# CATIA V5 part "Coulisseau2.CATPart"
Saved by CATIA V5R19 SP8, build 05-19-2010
Part number: Coulisseau2
Bounding box of the stored display mesh (mm): x -7.5 to 3.5, y -33.632 to -22.368, z -4.258 to 4.258
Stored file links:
  C:\Users\ThinkMotion\Desktop\EU_thinkMotion\iao\IAO_MMS_Groupe3\pmayet\pmayet_avant_optimisation\pmayet_avant_optimisation\Coulisseau2.CATPart
  C:\Users\ThinkMotion\Desktop\EU_thinkMotion\iao\IAO_MMS_Groupe3\pmayet\pmayet_avant_optimisation\pmayet_avant_optimisation\pmayet.CATProduct
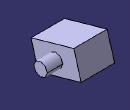
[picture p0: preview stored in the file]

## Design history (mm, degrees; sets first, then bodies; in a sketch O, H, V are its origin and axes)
Parameters
  Largeur_rainure_a = 6 mm
  Longueur_coulisseau = 10 mm
  Rayon_axe = 1.5 mm
  Epaisseu_disque = 15 mm
  Longueur_axe = 3.5 mm
Set1
  Plane1: linked copy from another document
  Line1: linked copy from another document
  Point1 "Point2": linked copy from another document
Body1 (main body)
  Sketch1 on Plane1, origin (0, 0, 0), H (0, 1, 0), V (0, 0, 1)
    line L1 (-33.6318, 1.511) -> (-24.0165, 4.2582)
    line L2 (-24.0165, 4.2582) -> (-22.3682, -1.511)
    line L3 (-22.3682, -1.511) -> (-31.9835, -4.2582)
    line L4 (-31.9835, -4.2582) -> (-33.6318, 1.511)
    reference projected line E1 (-28, 0) -> (0, 8) from Line1
    reference projected line E2 (-28, 0) -> (0, 8) from Line1
    reference projected line E3 (-28, 0) -> (0, 8) from Line1
    reference projected line E4 (-28, 0) -> (0, 8) from Line1
    reference projected point E5 (-28, 0) from Point1
    reference projected point E6 (-28, 0) from Point1
    distance E1 L1 = 3 {= Largeur_rainure_a /2}
    distance E3 L3 = 3 {= Largeur_rainure_a /2}
    distance E5 L4 = 5 {= Longueur_coulisseau /2}
    distance E6 L2 = 5 {= Longueur_coulisseau /2}
    parallelism: E2 L1, E4 L3
    perpendicularity: L1 L4, L2 L3
  Pad1: profile Sketch1, direction (-1, 0, 0), length 7.5 {= Epaisseu_disque /2}
  Sketch2 on Plane1, origin (0, 0, 0), H (0, 1, 0), V (0, 0, 1)
    circle A1 centre (-28, 0) radius 1.5
    point P1 (-28, 0)
    reference projected point E1 (-28, 0) from Point1
    distance P1 A1 = 1.5 {= Rayon_axe}
    coincidence: E1 P1
  Pad2: profile Sketch2, direction (1, 0, 0), length 3.5 {= Longueur_axe}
